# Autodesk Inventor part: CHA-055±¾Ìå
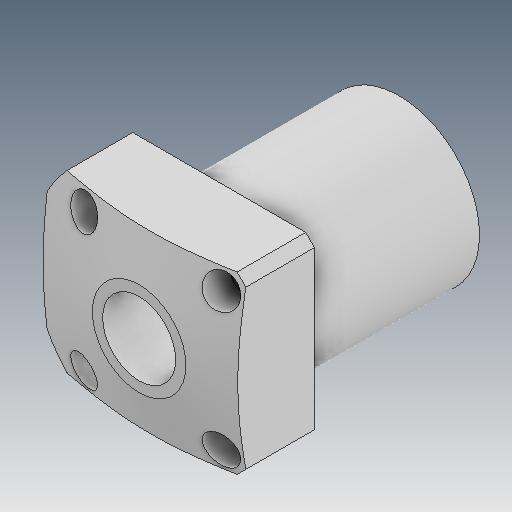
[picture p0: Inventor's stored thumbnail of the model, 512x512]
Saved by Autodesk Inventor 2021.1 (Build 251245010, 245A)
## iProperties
Created: 2019-12
Part Number: CHA-055±¾Ìå
Material: Ogólny
Document SubType Name: Modeling
Designer: user
Density: 1 g/cm^3
Appearance: Domyślna
Author: user
Revision Number: ÈÎºÎ
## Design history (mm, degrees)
feature "ÇÐ³ý-À­Éì7"
node "Bryła1"
